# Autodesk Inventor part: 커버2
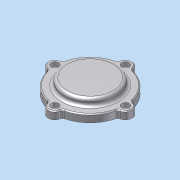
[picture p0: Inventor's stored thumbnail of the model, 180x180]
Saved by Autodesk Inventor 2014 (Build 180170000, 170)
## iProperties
Company: 한국ATC센터
Created: 2015-03
Part Number: 커버2
Document SubType Name: Modeling
Designer: KYOUNG IL JANG
Density: 1 g/cm^3
Material: 일반
Appearance: 기본값
Author: KYOUNG IL JANG
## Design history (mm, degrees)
sketch "스케치1"
  geometry: C1 r 1.621 at (0, 6.75) reference; C2 r 1.621 at (-37, -30.25) reference; C3 r 1.621 at (0, -67.25) reference; C4 r 1.621 at (37, -30.25) reference; C5 r 10 at (0, -30.25) reference; C6 r 12 at (0, -30.25); C7 r 24.5 at (0, -30.25) reference; A1 r 3 centre (-38.77, -20.408) between (-38.239, -23.361) and (-35.862, -21.146) reference; A2 r 7 centre (-37, -30.25) between (-38.239, -23.361) and (-38.239, -37.139) reference; A3 r 3 centre (-38.77, -40.092) between (-35.862, -39.354) and (-38.239, -37.139) reference; A4 r 37 centre (0, -30.25) between (-35.862, -39.354) and (-9.104, -66.113) reference; A5 r 3 centre (-9.842, -69.02) between (-6.889, -68.489) and (-9.104, -66.113) reference; A6 r 7 centre (0, -67.25) between (-6.889, -68.489) and (6.889, -68.489) reference; A7 r 3 centre (9.842, -69.02) between (9.104, -66.112) and (6.889, -68.489) reference; A8 r 37 centre (0, -30.25) between (9.104, -66.112) and (35.863, -39.354) reference; A9 r 3 centre (38.77, -40.092) between (38.239, -37.139) and (35.863, -39.354) reference; A10 r 7 centre (37, -30.25) between (38.239, -37.139) and (38.239, -23.361) reference; A11 r 3 centre (38.77, -20.408) between (35.863, -21.146) and (38.239, -23.361) reference; A12 r 37 centre (0, -30.25) between (35.863, -21.146) and (9.104, 5.612) reference; A13 r 3 centre (9.842, 8.52) between (6.889, 7.989) and (9.104, 5.612) reference; A14 r 7 centre (0, 6.75) between (6.889, 7.989) and (-6.889, 7.989) reference; A15 r 3 centre (-9.842, 8.52) between (-9.104, 5.612) and (-6.889, 7.989) reference; A16 r 37 centre (0, -30.25) between (-9.104, 5.612) and (-35.862, -21.146) reference; 1 further point
  constraints: 1 centre point, 1 coincident
  dimensions: "d2" = 2 radial gap between concentric circles of C6 C5
extrude "돌출1" new body sketch "스케치1" distance "d0" = 8; taper "d1" = 0 deg
sketch "스케치2"
  geometry: C1 r 23.5 at (0, -30.25) reference; C2 r 12 at (0, -30.25) reference; 1 further point
extrude "돌출2" join sketch "스케치2" distance "d4" = 5; taper "d5" = 0 deg
sketch "스케치3"
  geometry: C1 r 23.5 at (0, 0) reference; C2 r 20.5 at (0, 0); 1 further point
  constraints: 1 centre point
  dimensions: "d6" = 3 radial gap between concentric circles of C2 C1
node "작업 평면1"
extrude "돌출3" join sketch "스케치3" stored distance "d7" = 5; taper "d8" = 0 deg
fillet "모깎기1" dims "d9" = 3
sketch "스케치4"
  geometry: C1 r 12 at (0, -30.25) reference; C2 r 27 at (0, -30.25); 1 further point
  constraints: 1 centre point
  dimensions: "d10" = 15 radial gap between concentric circles of C1 C2
extrude "돌출4" join sketch "스케치4" distance "d11" = 7; taper "d12" = 0 deg
fillet "모깎기2" dims "d13" = 3
chamfer "모따기1" distance "d14" = 1; stored, may be unused: second distance "d15" = 2, angle "d16" = 45 deg
node "작업점1"
  node "작업축1"
chamfer "모따기2" distance "d24" = 1; stored, may be unused: second distance "d25" = 2, angle "d26" = 45 deg
hole "구멍6" diameter "d43" = 4.5; stored, may be unused: countersink angle "d47" = 90 deg, drill point angle "d49" = 118 deg; dims "d41" = 10, "d42" = 10, "d44" = 6, "d45" = 8, "d46" = 4.4, "d48" = 8
fillet "모깎기4" dims "d60" = 3
node "솔리드1"
pattern_circular "원형 패턴1" dims angle "d51" = 360 deg
node "참조1"
node "참조2"
